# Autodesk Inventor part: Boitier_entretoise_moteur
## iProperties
Shininess: 64.0
Length Units: 11269
Angle Units: 11279
Time Units: 11290
Mass Units: 11283
Length Display Precision: 3
Angle Display Precision: 2
Compacted: True
Part Number: Boitier_entretoise_moteur
Document SubType Name: Modeling
Created: 2008-02
Material: Acier inoxydable - 440C
Designer: Pascal
Density: 0.0
Volumn: 0.0
Area: 0.0
PropertySet Name: Model Information
Control State: 0
Master: False
Checked Out: False
DESIGNATION: pièce
Author: Pascal
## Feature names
1. Révolution1 [Revolution]
